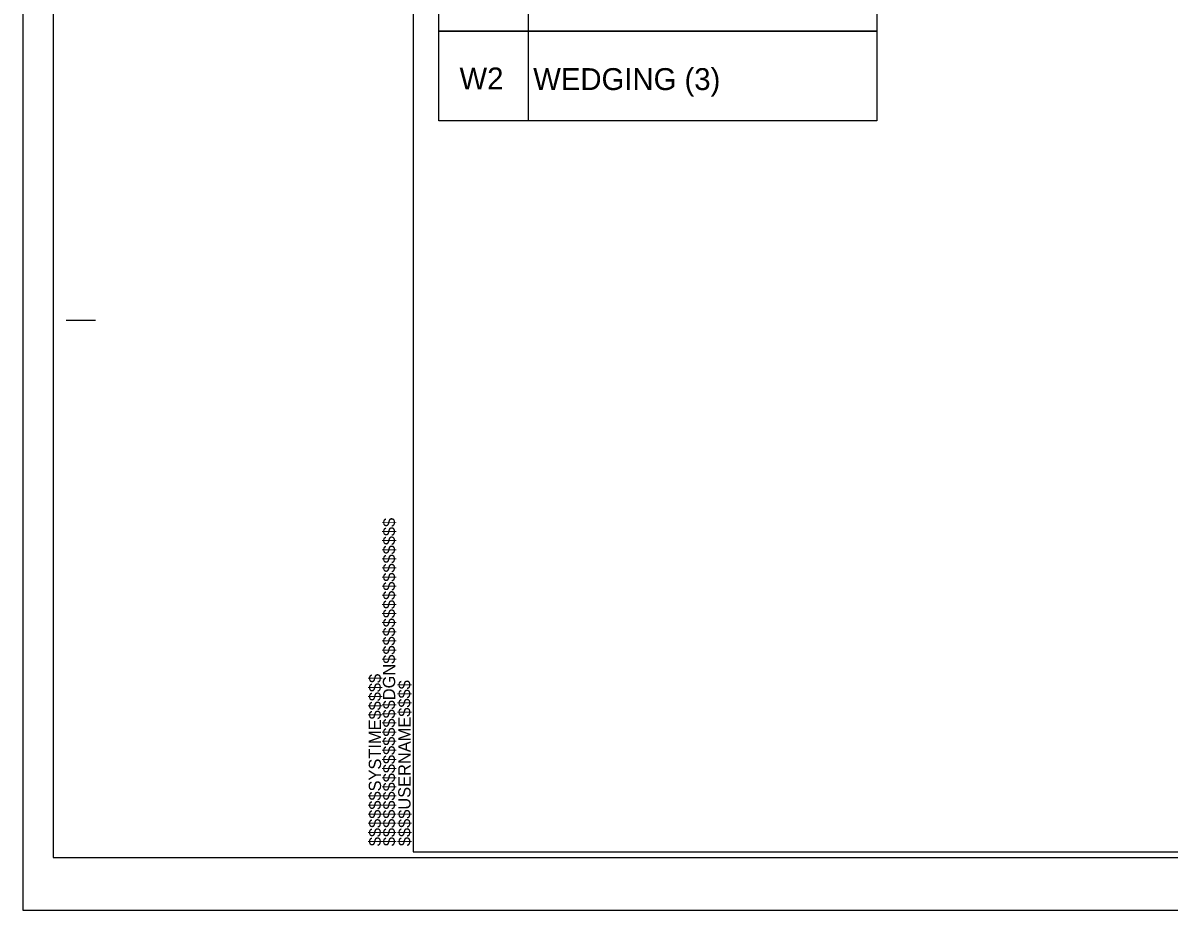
# Model space of a CAD drawing. Extents: x 3025871 to 3026431, y 707165 to 707825.
# Drawn here: x 3026022 to 3026095.6, y 707222.4 to 707279.4 of the extents above; entities that cross this region are included whole.
import ezdxf

# ---------------------------------------------------------------- set-up
doc = ezdxf.new("R2010")
doc.units = 0
for name, color, linetype in [('Old_Level_39', 7, 'Continuous'), ('Sheet Cutting Line CELL', 7, 'Continuous'), ('Typical ID Circle CELL', 7, 'Continuous'), ('Typical Terminator CELL', 7, 'Continuous')]:
    doc.layers.add(name, color=color, linetype=linetype)

msp = doc.modelspace()

# ---------------------------------------------------------------- linework, layer by layer
at = {"layer": 'Old_Level_39'}
msp.add_lwpolyline([(3026273.948, 707384.017), (3026023.973, 707384.017), (3026023.973, 707225.752), (3026273.948, 707225.752)], close=True, dxfattribs=at)
at = {"layer": 'Sheet Cutting Line CELL'}
for p, q in [((3026024.798, 707260.26), (3026026.673, 707260.26)), ((3026047.073, 707226.135), (3026047.073, 707226.135)), ((3026047.073, 707226.135), (3026047.073, 707226.135)), ((3026047.073, 707226.135), (3026047.073, 707226.135)), ((3026047.073, 707226.135), (3026047.073, 707226.135)), ((3026047.073, 707226.135), (3026047.073, 707226.135)), ((3026047.073, 707226.135), (3026047.073, 707226.135))]:
    msp.add_line(p, q, dxfattribs=at)
msp.add_lwpolyline([(3026272.073, 707383.635), (3026047.073, 707383.635), (3026047.073, 707226.135), (3026272.073, 707226.135)], close=True, dxfattribs=at)
msp.add_lwpolyline([(3026052.698, 707226.135), (3026052.698, 707226.135)], dxfattribs=at)
at = {"layer": 'Typical ID Circle CELL'}
for points in [[(3026054.475, 707278.814), (3026048.722, 707278.814), (3026048.722, 707284.566), (3026076.847, 707284.566), (3026076.847, 707278.814), (3026054.475, 707278.814), (3026054.475, 707284.566)], [(3026054.475, 707273.061), (3026048.722, 707273.061), (3026048.722, 707278.814), (3026076.847, 707278.814), (3026076.847, 707273.061), (3026054.475, 707273.061), (3026054.475, 707278.814)]]:
    msp.add_lwpolyline(points, dxfattribs=at)
at = {"layer": 'Typical Terminator CELL'}
msp.add_lwpolyline([(3026274.623, 707387.385), (3026022.023, 707387.385), (3026022.023, 707222.385), (3026274.623, 707222.385)], close=True, dxfattribs=at)

# ---------------------------------------------------------------- texts
at = {"layer": 'Sheet Cutting Line CELL'}
for s, p in [('$$$$$$$$$$$$$$$$DGN$$$$$$$$$$$$$$$$', (3026045.925, 707226.489)), ('$$$$$$SYSTIME$$$$$', (3026045.018, 707226.489)), ('$$$$USERNAME$$$$', (3026046.911, 707226.491))]:
    msp.add_text(s, height=0.7875, rotation=90, dxfattribs=at).set_placement(p)
at = {"layer": 'Typical ID Circle CELL'}
for s, height, p in [('W2', 1.4062, (3026050.056, 707275.081)), ('WEDGING (3)', 1.40625, (3026054.789, 707275.041))]:
    msp.add_text(s, height=height, dxfattribs=at).set_placement(p)

doc.saveas('drawing.dxf')
